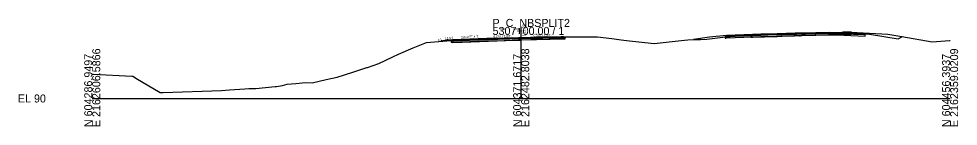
# Model space of a CAD drawing. Extents: x -26 to 1303, y -10 to 12038.
# Drawn here: x 974.3 to 1302.8, y 1490.3 to 1527.8 of the extents above; entities that cross this region are included whole.
import ezdxf

# ---------------------------------------------------------------- set-up
doc = ezdxf.new("R2010")
doc.units = 0
for name, color, linetype in [('RD_GPK_XS_Cell', 7, 'Continuous'), ('RD_XS_Base', 7, 'Continuous'), ('RD_XS_ExGround', 7, 'Continuous'), ('RD_XS_ExPaveRet', 7, 'Continuous'), ('RD_XS_Greenside', 7, 'Continuous'), ('RD_XS_Pave', 7, 'Continuous'), ('RD_XS_PaveOvlay_CP', 7, 'Continuous'), ('RD_XS_TieSlope', 7, 'Continuous'), ('RD_XS_TX_Elev_EX', 7, 'Continuous'), ('RD_XS_TX_Elev_PR', 7, 'Continuous'), ('RD_XS_TX_ShdSlope', 7, 'Continuous'), ('RD_XS_TX_Slope', 7, 'Continuous')]:
    doc.layers.add(name, color=color, linetype=linetype)

msp = doc.modelspace()

# ---------------------------------------------------------------- linework, layer by layer
at = {"layer": 'RD_GPK_XS_Cell'}
for p, q in [((1150, 1500), (1150, 1525)), ((1000, 1500), (1150, 1500)), ((1150, 1500), (1300, 1500))]:
    msp.add_line(p, q, dxfattribs=at)
at = {"layer": 'RD_XS_Base'}
for p, q in [((1150, 1520.91), (1165.26, 1521.24)), ((1164.76, 1521.23), (1164.76, 1521.23)), ((1165.26, 1521.24), (1165.26, 1520.74)), ((1165.26, 1521.21), (1165.26, 1521.21)), ((1221.63, 1521.63), (1221.33, 1521.62)), ((1221.33, 1521.62), (1221.33, 1521.42)), ((1221.33, 1521.42), (1221.33, 1521.12)), ((1221.33, 1521.12), (1221.63, 1521.13)), ((1221.83, 1521.64), (1221.63, 1521.63)), ((1221.63, 1521.13), (1221.83, 1521.14)), ((1227.9, 1521.88), (1221.83, 1521.64)), ((1221.83, 1521.14), (1227.9, 1521.38)), ((1233.83, 1522.12), (1227.9, 1521.88)), ((1227.9, 1521.38), (1233.83, 1521.62)), ((1236.33, 1522.19), (1233.83, 1522.12)), ((1233.83, 1521.62), (1236.33, 1521.69)), ((1245.83, 1522.45), (1236.33, 1522.19)), ((1236.33, 1521.69), (1245.83, 1521.95)), ((1253.06, 1522.66), (1245.83, 1522.45)), ((1245.83, 1522.55), (1245.83, 1522.61)), ((1245.83, 1522.61), (1245.83, 1522.35)), ((1245.83, 1522.45), (1245.83, 1522.55)), ((1245.83, 1522.45), (1245.83, 1522.45)), ((1245.83, 1522.45), (1245.83, 1522.45)), ((1245.83, 1522.26), (1245.83, 1522.45)), ((1245.83, 1522.35), (1245.83, 1521.95)), ((1245.83, 1521.95), (1245.83, 1522.26)), ((1245.83, 1521.95), (1253.06, 1522.16)), ((1257.83, 1522.79), (1253.06, 1522.66)), ((1253.06, 1522.16), (1257.83, 1522.29)), ((1262.59, 1522.6), (1257.83, 1522.79)), ((1257.83, 1522.29), (1262.79, 1522.09)), ((1269.83, 1522.31), (1262.59, 1522.6)), ((1262.79, 1522.09), (1270.33, 1521.79)), ((1270.02, 1522.3), (1269.83, 1522.31)), ((1270.33, 1522.29), (1270.02, 1522.3)), ((1270.33, 1522.09), (1270.33, 1522.29)), ((1270.33, 1521.79), (1270.33, 1522.09)), ((1126, 1520.17), (1125.5, 1520.15)), ((1125.5, 1520.15), (1125.5, 1520.15)), ((1125.5, 1520.15), (1125.5, 1519.65)), ((1125.5, 1519.65), (1126, 1519.67)), ((1138, 1520.65), (1126, 1520.17)), ((1126, 1520.17), (1126, 1520.17)), ((1126, 1519.67), (1138, 1520.15)), ((1126, 1519.67), (1126, 1519.67)), ((1150, 1520.91), (1138, 1520.65)), ((1138, 1520.65), (1138, 1520.65)), ((1138, 1520.15), (1150, 1520.41)), ((1138, 1520.15), (1138, 1520.15)), ((1150, 1520.41), (1150, 1521.07)), ((1150, 1521.07), (1150, 1521.07)), ((1150, 1521.07), (1150, 1521.07)), ((1150, 1521.07), (1150, 1520.91)), ((1150, 1520.91), (1150, 1520.91)), ((1150, 1520.41), (1150, 1520.91)), ((1150, 1520.91), (1150, 1520.91)), ((1150, 1520.91), (1150, 1520.91)), ((1165.26, 1520.74), (1150, 1520.41)), ((1150, 1520.41), (1150, 1520.41)), ((1165.26, 1520.71), (1165.26, 1520.71)), ((1165.26, 1520.71), (1165.26, 1520.71))]:
    msp.add_line(p, q, dxfattribs=at)
at = {"layer": 'RD_XS_ExGround'}
msp.add_lwpolyline([(1000, 1508.5), (1000.48, 1508.52), (1013.88, 1507.79), (1014.15, 1507.78), (1014.37, 1507.65), (1015.26, 1507.11), (1023.79, 1502.06), (1024.85, 1502.09), (1045.15, 1502.79), (1046.6, 1502.91), (1047.95, 1502.99), (1053.4, 1503.41), (1054.75, 1503.43), (1057.22, 1503.49), (1064.01, 1504.15), (1064.44, 1504.22), (1066.57, 1504.58), (1068.22, 1504.96), (1071.17, 1505.27), (1074.6, 1505.56), (1076.94, 1505.45), (1081.82, 1506.61), (1085.65, 1507.43), (1091.11, 1509.2), (1096.03, 1510.82), (1096.26, 1510.87), (1100.22, 1512.23), (1104.93, 1514.46), (1105.1, 1514.56), (1107.1, 1515.5), (1112.22, 1517.68), (1116.93, 1519.53), (1123.99, 1520.18), (1125.48, 1520.3), (1126.08, 1520.35), (1129.37, 1520.47), (1144.65, 1521.02), (1149.02, 1521.19), (1150.07, 1521.23), (1153.32, 1521.34), (1155.4, 1521.41), (1163.93, 1521.54), (1164.64, 1521.55), (1165.02, 1521.55), (1165.41, 1521.56), (1167.19, 1521.53), (1176.7, 1521.49), (1181.74, 1520.9), (1184.93, 1520.5), (1186.81, 1520.29), (1196.54, 1519.19), (1205.94, 1520.28), (1208.33, 1520.5), (1210.92, 1520.56), (1212.76, 1520.59), (1214.94, 1520.78), (1221.5, 1521.5), (1227.89, 1521.98), (1230.48, 1522.2), (1240.72, 1522.5), (1240.94, 1522.5), (1240.97, 1522.5), (1245.57, 1522.66), (1245.94, 1522.74), (1246.21, 1522.7), (1246.33, 1522.74), (1247.31, 1522.67), (1261.48, 1523.09), (1263.72, 1523.15), (1265.52, 1523.19), (1266.89, 1523.11), (1267.48, 1523.08), (1278.21, 1522.5), (1283.16, 1521.63), (1293.77, 1519.78), (1299.77, 1520.25), (1300, 1520.27)], dxfattribs=at)
at = {"layer": 'RD_XS_ExPaveRet'}
for points in [[(1163.93, 1521.54), (1155.4, 1521.41), (1155.4, 1521.41), (1153.32, 1521.34), (1153.32, 1521.34), (1150.07, 1521.23), (1150.07, 1521.23), (1150.07, 1521.23), (1149.02, 1521.19), (1149.02, 1521.19), (1144.65, 1521.02), (1144.65, 1521.02), (1129.37, 1520.47), (1129.37, 1520.47), (1126.08, 1520.35), (1126.08, 1520.35), (1126.08, 1520.35), (1126.08, 1519.6), (1126.08, 1519.6), (1129.37, 1519.72), (1129.37, 1519.72), (1144.65, 1520.27), (1144.65, 1520.27), (1149.02, 1520.44), (1149.02, 1520.44), (1150.07, 1520.48), (1150.07, 1520.48), (1150.07, 1520.48), (1153.32, 1520.59), (1153.32, 1520.59), (1155.4, 1520.66), (1155.4, 1520.66), (1163.93, 1520.79), (1163.93, 1520.79), (1164.64, 1520.8), (1164.64, 1521.55), (1164.64, 1521.55), (1163.93, 1521.54), (1163.93, 1521.54)], [(1163.93, 1521.54), (1155.4, 1521.41), (1153.32, 1521.34), (1150.07, 1521.23), (1149.02, 1521.19), (1144.65, 1521.02), (1129.37, 1520.47), (1126.08, 1520.35), (1126.08, 1520.35), (1126.08, 1519.6), (1126.08, 1519.6), (1129.37, 1519.72), (1144.65, 1520.27), (1149.02, 1520.44), (1150.07, 1520.48), (1153.32, 1520.59), (1155.4, 1520.66), (1163.93, 1520.79), (1164.64, 1520.8), (1164.64, 1521.55), (1163.93, 1521.54)], [(1264.25, 1523.16), (1265.52, 1523.19), (1265.52, 1523.14), (1265.52, 1522.44), (1264.25, 1522.41), (1262.66, 1522.37), (1262.13, 1522.36), (1248.17, 1521.95), (1247.54, 1521.93), (1247.31, 1521.92), (1246.34, 1521.99), (1246.33, 1521.99), (1246.33, 1521.99), (1246.21, 1521.95), (1246.18, 1521.95), (1245.94, 1521.99), (1245.92, 1521.98), (1245.57, 1521.91), (1245.34, 1521.9), (1241.23, 1521.76), (1241.14, 1521.76), (1240.94, 1521.76), (1239.48, 1521.71), (1239.25, 1521.7), (1230.98, 1521.46), (1230.48, 1521.45), (1230.48, 1522.15), (1230.48, 1522.2), (1230.98, 1522.21), (1239.25, 1522.45), (1239.48, 1522.46), (1240.94, 1522.51), (1241.14, 1522.51), (1241.23, 1522.51), (1245.34, 1522.65), (1245.57, 1522.66), (1245.92, 1522.73), (1245.94, 1522.74), (1246.18, 1522.7), (1246.21, 1522.7), (1246.33, 1522.74), (1246.33, 1522.74), (1246.34, 1522.74), (1247.31, 1522.67), (1247.54, 1522.68), (1248.17, 1522.7), (1262.13, 1523.11), (1262.66, 1523.12), (1264.25, 1523.16)], [(1262.66, 1523.12), (1262.13, 1523.11), (1248.17, 1522.7), (1247.54, 1522.68), (1247.31, 1522.67), (1246.34, 1522.74), (1246.33, 1522.74), (1246.33, 1522.74), (1246.21, 1522.7), (1246.18, 1522.7), (1245.94, 1522.74), (1245.92, 1522.73), (1245.57, 1522.66), (1245.34, 1522.65), (1241.23, 1522.51), (1241.14, 1522.51), (1240.94, 1522.51), (1239.48, 1522.46), (1239.25, 1522.45), (1230.98, 1522.21), (1230.48, 1522.2), (1230.48, 1522.15), (1230.48, 1521.45), (1230.98, 1521.46), (1239.25, 1521.7), (1239.48, 1521.71), (1240.94, 1521.76), (1241.14, 1521.76), (1241.23, 1521.76), (1245.34, 1521.9), (1245.57, 1521.91), (1245.92, 1521.98), (1245.94, 1521.99), (1246.18, 1521.95), (1246.21, 1521.95), (1246.33, 1521.99), (1246.33, 1521.99), (1246.34, 1521.99), (1247.31, 1521.92), (1247.54, 1521.93), (1248.17, 1521.95), (1262.13, 1522.36), (1262.66, 1522.37), (1264.25, 1522.41), (1265.52, 1522.44), (1265.52, 1523.14), (1265.52, 1523.19), (1264.25, 1523.16), (1262.66, 1523.12)]]:
    msp.add_lwpolyline(points, dxfattribs=at)
at = {"layer": 'RD_XS_Greenside'}
for p, q in [((1215.83, 1521.48), (1210.24, 1520.55)), ((1271.83, 1522.47), (1281.83, 1520.8)), ((1281.83, 1520.8), (1283.41, 1521.6)), ((1124, 1520.33), (1121.96, 1519.99))]:
    msp.add_line(p, q, dxfattribs=at)
at = {"layer": 'RD_XS_Pave'}
for p, q in [((1150, 1521.23), (1138, 1520.97)), ((1164.76, 1521.55), (1150, 1521.23)), ((1164.76, 1521.39), (1150, 1521.07)), ((1150, 1521.07), (1164.76, 1521.39)), ((1150, 1520.91), (1164.76, 1521.23)), ((1150, 1521.23), (1150, 1521.23)), ((1164.76, 1521.39), (1164.76, 1521.55)), ((1164.76, 1521.55), (1164.76, 1521.55)), ((1164.76, 1521.23), (1164.76, 1521.39)), ((1164.76, 1521.39), (1164.76, 1521.39)), ((1164.76, 1521.39), (1164.76, 1521.39)), ((1164.76, 1521.39), (1164.76, 1521.39)), ((1164.76, 1521.23), (1164.76, 1521.23)), ((1164.76, 1521.23), (1164.76, 1521.23)), ((1227.9, 1522.2), (1221.83, 1521.96)), ((1227.9, 1522.04), (1221.83, 1521.8)), ((1221.83, 1521.8), (1227.9, 1522.04)), ((1221.83, 1521.96), (1221.83, 1521.89)), ((1221.83, 1521.89), (1221.83, 1521.8)), ((1221.83, 1521.64), (1227.9, 1521.88)), ((1221.83, 1521.8), (1221.83, 1521.74)), ((1221.83, 1521.74), (1221.83, 1521.64)), ((1233.83, 1522.44), (1227.9, 1522.2)), ((1233.83, 1522.28), (1227.9, 1522.04)), ((1227.9, 1522.04), (1233.83, 1522.28)), ((1227.9, 1521.88), (1233.83, 1522.12)), ((1236.33, 1522.51), (1233.83, 1522.44)), ((1236.33, 1522.35), (1233.83, 1522.28)), ((1233.83, 1522.28), (1236.33, 1522.35)), ((1233.83, 1522.12), (1236.33, 1522.19)), ((1245.83, 1522.77), (1236.33, 1522.51)), ((1245.83, 1522.61), (1236.33, 1522.35)), ((1236.33, 1522.35), (1245.83, 1522.61)), ((1236.33, 1522.19), (1245.83, 1522.45)), ((1253.06, 1522.98), (1245.83, 1522.77)), ((1253.06, 1522.82), (1245.83, 1522.61)), ((1245.83, 1522.61), (1253.06, 1522.82)), ((1245.83, 1522.45), (1253.06, 1522.66)), ((1245.83, 1522.55), (1245.83, 1522.61)), ((1245.83, 1522.61), (1245.83, 1522.61)), ((1245.83, 1522.61), (1245.83, 1522.61)), ((1245.83, 1522.61), (1245.83, 1522.55)), ((1245.83, 1522.45), (1245.83, 1522.55)), ((1245.83, 1522.55), (1245.83, 1522.45)), ((1245.83, 1522.45), (1245.83, 1522.45)), ((1245.83, 1522.45), (1245.83, 1522.45)), ((1257.83, 1523.11), (1253.06, 1522.98)), ((1257.83, 1522.95), (1253.06, 1522.82)), ((1253.06, 1522.82), (1257.83, 1522.95)), ((1253.06, 1522.66), (1257.83, 1522.79)), ((1262.59, 1522.92), (1257.83, 1523.11)), ((1262.59, 1522.76), (1257.83, 1522.95)), ((1257.83, 1522.95), (1262.59, 1522.76)), ((1257.83, 1522.79), (1262.59, 1522.6)), ((1269.83, 1522.63), (1262.59, 1522.92)), ((1269.83, 1522.47), (1262.59, 1522.76)), ((1262.59, 1522.76), (1269.83, 1522.47)), ((1262.59, 1522.6), (1269.83, 1522.31)), ((1269.83, 1522.57), (1269.83, 1522.63)), ((1269.83, 1522.47), (1269.83, 1522.57)), ((1269.83, 1522.41), (1269.83, 1522.47)), ((1269.83, 1522.31), (1269.83, 1522.41)), ((1138, 1520.97), (1126, 1520.49)), ((1126, 1520.33), (1138, 1520.81)), ((1138, 1520.81), (1126, 1520.33)), ((1126, 1520.17), (1138, 1520.65)), ((1126, 1520.49), (1126, 1520.49)), ((1126, 1520.49), (1126, 1520.33)), ((1126, 1520.33), (1126, 1520.33)), ((1126, 1520.33), (1126, 1520.17)), ((1138, 1520.81), (1150, 1521.07)), ((1150, 1521.07), (1138, 1520.81)), ((1138, 1520.97), (1138, 1520.97)), ((1138, 1520.65), (1150, 1520.91)), ((1138, 1520.81), (1138, 1520.81)), ((1138, 1520.81), (1138, 1520.81)), ((1138, 1520.65), (1138, 1520.65)), ((1150, 1521.07), (1150, 1521.07)), ((1150, 1521.07), (1150, 1521.07)), ((1150, 1521.07), (1150, 1520.91)), ((1150, 1521.07), (1150, 1521.07)), ((1150, 1520.91), (1150, 1521.07)), ((1150, 1521.07), (1150, 1521.07)), ((1150, 1521.07), (1150, 1521.07)), ((1150, 1520.91), (1150, 1520.91)), ((1150, 1520.91), (1150, 1520.91))]:
    msp.add_line(p, q, dxfattribs=at)
at = {"layer": 'RD_XS_PaveOvlay_CP'}
for p, q in [((1150, 1521.23), (1138, 1520.97)), ((1164.76, 1521.55), (1150, 1521.23)), ((1150, 1521.23), (1150, 1521.23)), ((1164.76, 1521.55), (1164.76, 1521.55)), ((1227.9, 1522.2), (1221.83, 1521.96)), ((1233.83, 1522.44), (1227.9, 1522.2)), ((1236.33, 1522.51), (1233.83, 1522.44)), ((1245.83, 1522.77), (1236.33, 1522.51)), ((1253.06, 1522.98), (1245.83, 1522.77)), ((1257.83, 1523.11), (1253.06, 1522.98)), ((1262.59, 1522.92), (1257.83, 1523.11)), ((1269.83, 1522.63), (1262.59, 1522.92)), ((1138, 1520.97), (1126, 1520.49)), ((1138, 1520.97), (1138, 1520.97))]:
    msp.add_line(p, q, dxfattribs=at)
at = {"layer": 'RD_XS_TieSlope'}
for p, q in [((1221.83, 1521.96), (1215.83, 1521.48)), ((1269.83, 1522.63), (1271.83, 1522.47)), ((1126, 1520.49), (1124, 1520.33))]:
    msp.add_line(p, q, dxfattribs=at)

# ---------------------------------------------------------------- texts
at = {"layer": 'RD_GPK_XS_Cell'}
for s, p in [('P_C_NBSPLIT2', (1140, 1525)), ('5307+00.00 / 1', (1140, 1522.2)), ('EL 90', (974, 1498.6))]:
    msp.add_text(s, height=2.8, dxfattribs=at).set_placement(p)
for s, p in [('N 604286.9497', (1000, 1490)), ('E 2162606.5866', (1002.8, 1490)), ('N 604371.6717', (1150, 1490)), ('E 2162482.8038', (1152.8, 1490)), ('N 604456.3937', (1300, 1490)), ('E 2162359.0209', (1302.8, 1490))]:
    msp.add_text(s, height=2.8, rotation=90, dxfattribs=at).set_placement(p)
at = {"layer": 'RD_XS_TX_Elev_EX'}
msp.add_text('111.23', height=0.6, rotation=90, dxfattribs=at).set_placement((1149.63, 1522.16))
at = {"layer": 'RD_XS_TX_Elev_PR'}
msp.add_text('111.23', height=1, rotation=90, dxfattribs=at).set_placement((1151.46, 1521.73))
at = {"layer": 'RD_XS_TX_ShdSlope'}
msp.add_text('12.5:1', height=0.75, rotation=4.5739, dxfattribs=at).set_placement((1123.41, 1520.64))
at = {"layer": 'RD_XS_TX_Slope'}
for s, rotation, p in [('0.040 FT./FT.', 2.2906, (1128.99, 1521.04)), ('0.028 FT./FT.', 1.6039, (1140.34, 1521.28)), ('0.028 FT./FT.', 1.6039, (1154.36, 1521.62)), ('4:1', 14.0362, (1120.92, 1520.02))]:
    msp.add_text(s, height=0.75, rotation=rotation, dxfattribs=at).set_placement(p)

doc.saveas('drawing.dxf')
